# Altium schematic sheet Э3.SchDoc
size 594 x 420 mm; CheckedBy: Шилкин Д. А.; Author: Шестаков А. А.
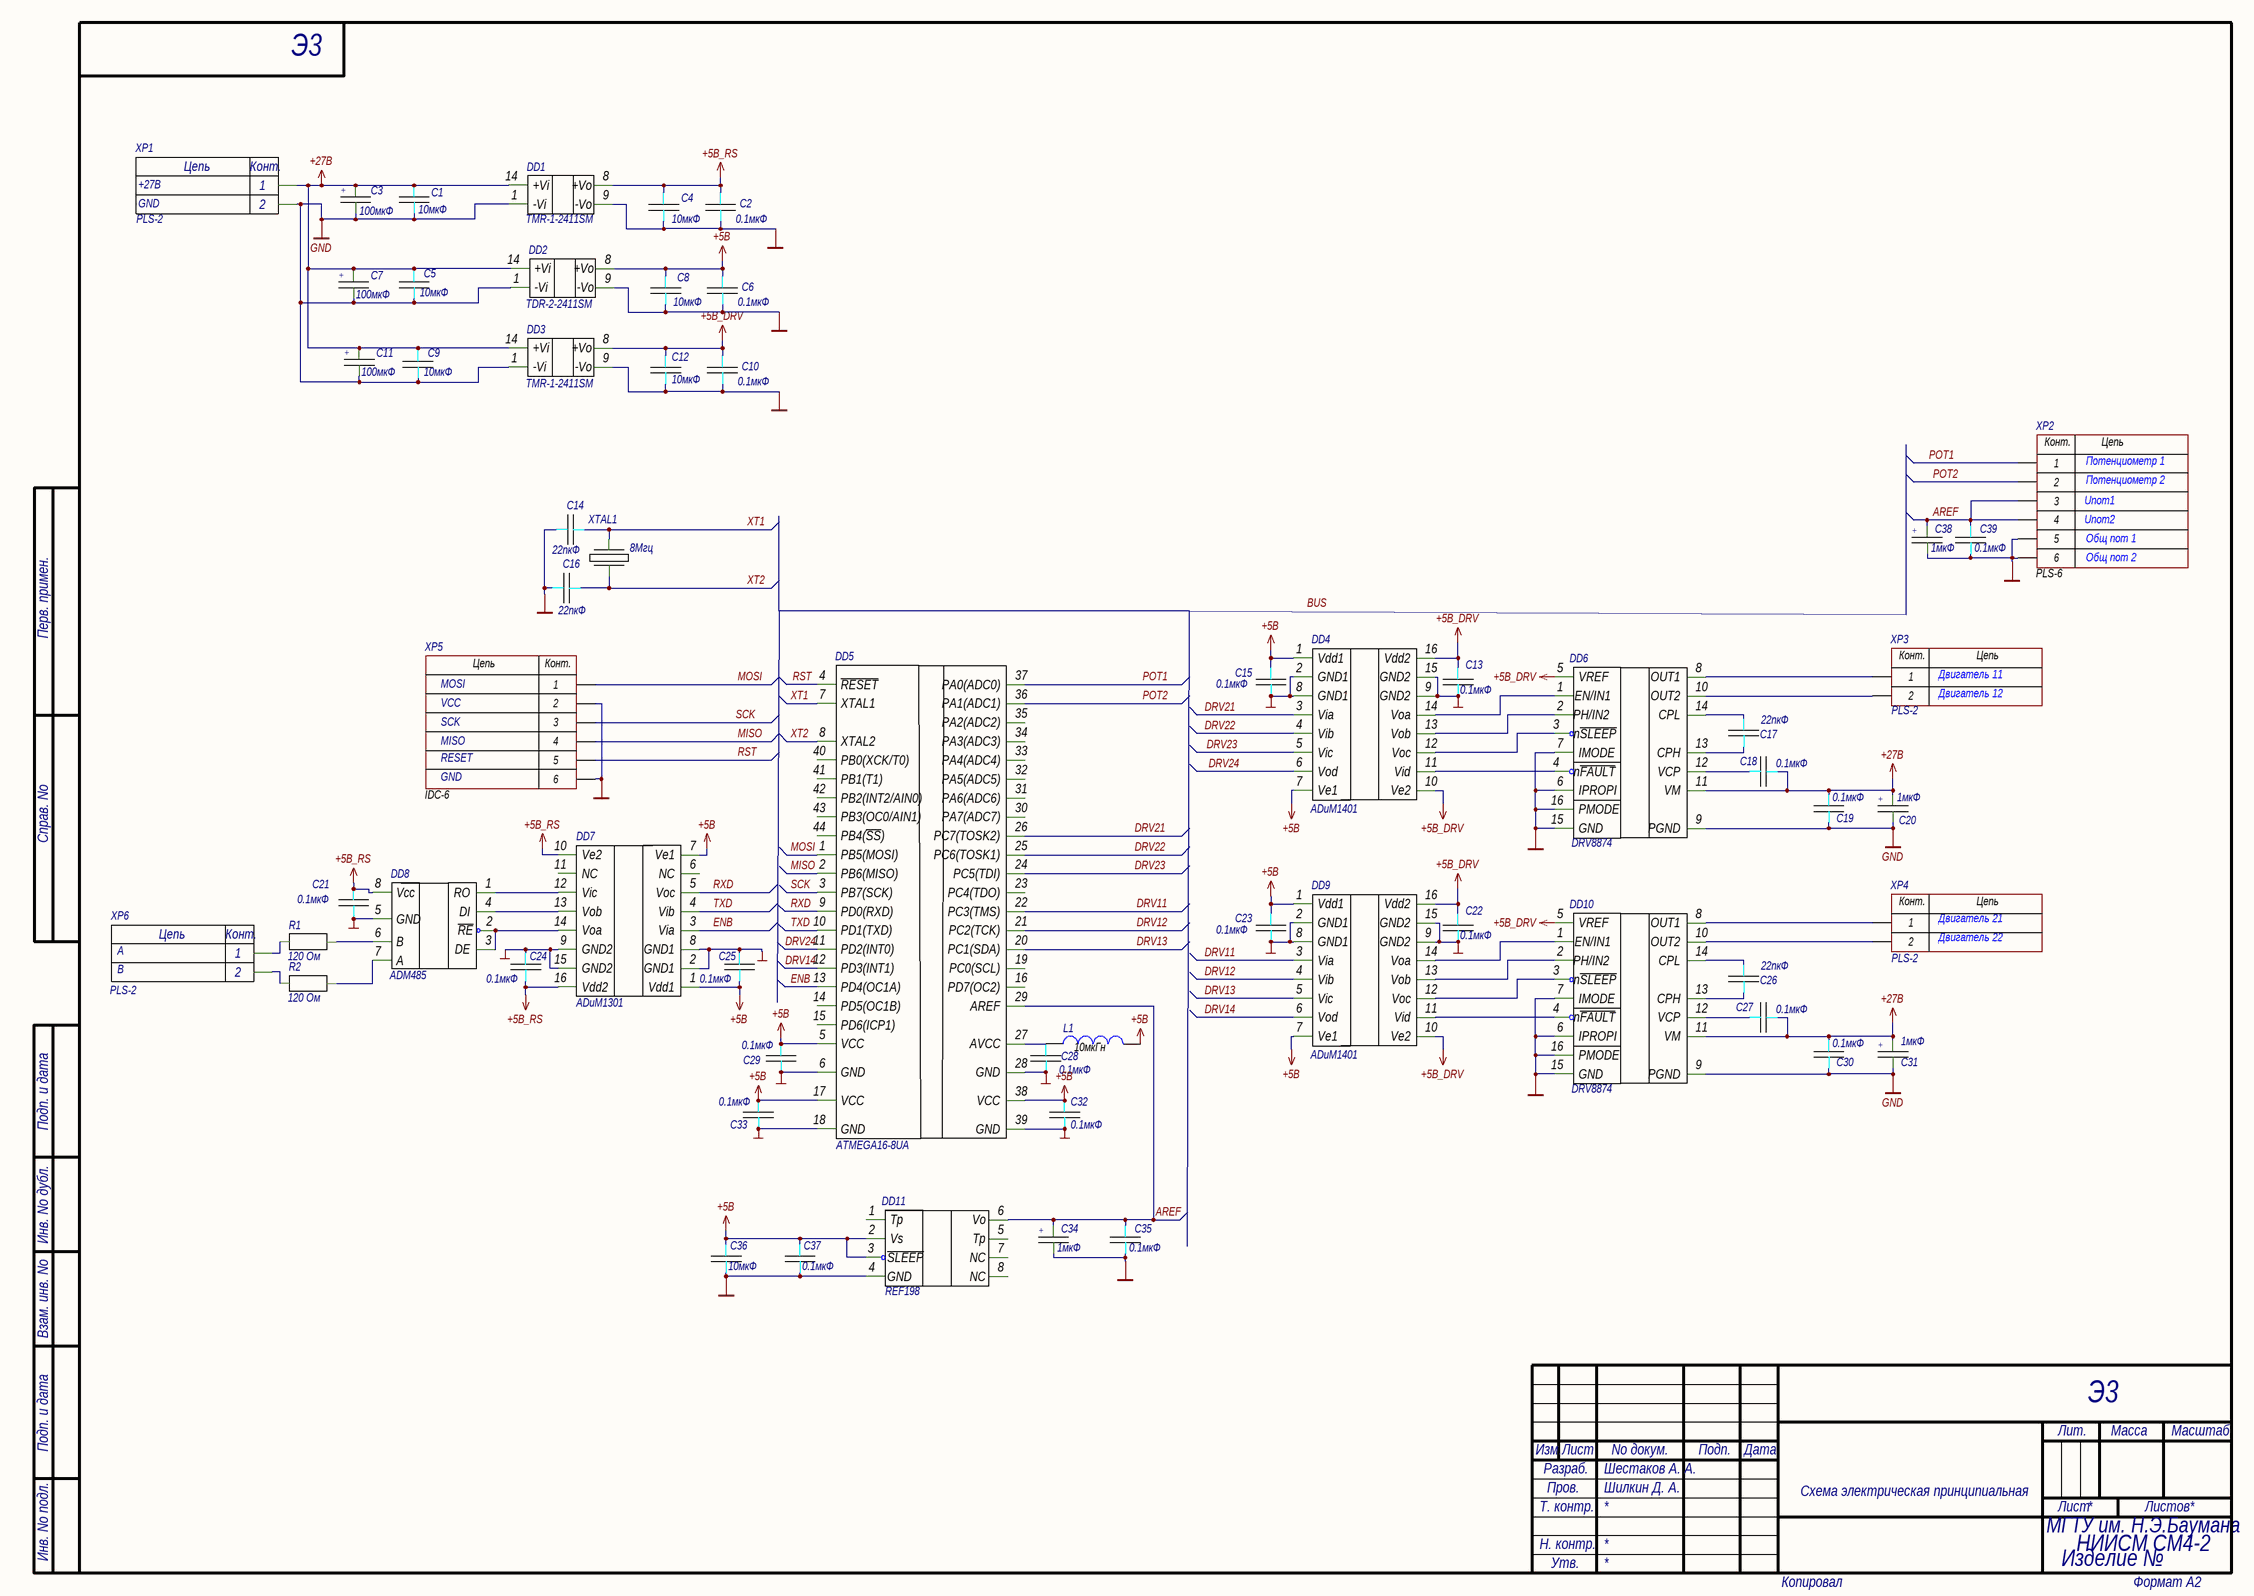
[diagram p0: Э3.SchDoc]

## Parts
C1  10мкФ  [Capacitor_0805]
C2  0.1мкФ  [Capacitor_0805]
C3  100мкФ  [CAPAE4643X46M]
C4  10мкФ  [Capacitor_0805]
C5  10мкФ  [Capacitor_0805]
C6  0.1мкФ  [Capacitor_0805]
C7  100мкФ  [CAPAE4643X46M]
C8  10мкФ  [Capacitor_0805]
C9  10мкФ  [Capacitor_0805]
C10  0.1мкФ  [Capacitor_0805]
C11  100мкФ  [CAPAE4643X46M]
C12  10мкФ  [Capacitor_0805]
C13  0.1мкФ  [Capacitor_0805]
C14  22пкФ  [Capacitor_0805]
C15  0.1мкФ  [Capacitor_0805]
C16  22пкФ  [Capacitor_0805]
C17  22пкФ  [Capacitor_0805]
C18  0.1мкФ  [Capacitor_0805]
C19  0.1мкФ  [Capacitor_0805]
C20  1мкФ  [Capacitor_tant_0805]
C21  0.1мкФ  [Capacitor_0805]
C22  0.1мкФ  [Capacitor_0805]
C23  0.1мкФ  [Capacitor_0805]
C24  0.1мкФ  [Capacitor_0805]
C25  0.1мкФ  [Capacitor_0805]
C26  22пкФ  [Capacitor_0805]
C27  0.1мкФ  [Capacitor_0805]
C28  0.1мкФ  [Capacitor_0805]
C29  0.1мкФ  [Capacitor_0805]
C30  0.1мкФ  [Capacitor_0805]
C31  1мкФ  [Capacitor_tant_0805]
C32  0.1мкФ  [Capacitor_0805]
C33  0.1мкФ  [Capacitor_0805]
C34  1мкФ  [Capacitor_tant_0805]
C35  0.1мкФ  [Capacitor_0805]
C36  10мкФ  [Capacitor_0805]
C37  0.1мкФ  [Capacitor_0805]
C38  1мкФ  [Capacitor_tant_0805]
C39  0.1мкФ  [Capacitor_0805]
DD1  TMR-1-2411SM  [TMR1SM_SMD]
DD2  TDR-2-2411SM  [TMR1SM_SMD]
DD3  TMR-1-2411SM  [TMR1SM_SMD]
DD4  ADuM1401  [ADUM_SOIC]
DD5  ATMEGA16-8UA  [ATMEGA16-44A]
DD6  DRV8874  [DRV8874_TSOP127P600-8N]
DD7  ADuM1301  [ADUM_SOIC]
DD8  ADM485  [SOIC_N8 (REF198, ADM485)]
DD9  ADuM1401  [ADUM_SOIC]
DD10  DRV8874  [DRV8874_TSOP127P600-8N]
DD11  REF198  [SOIC_N8 (REF198, ADM485)]
L1  value 10мкГн  [IND: 0805]
R1  120 Ом  [resistor_0805]
R2  120 Ом  [resistor_0805]
XP1  PLS-2  [CON: PLS-2]
XP2  (no value)  [CON: PLS-6]
XP3  PLS-2  [CON: PLS-2]
XP4  PLS-2  [CON: PLS-2]
XP5  (no value)  [CON: IDC-6MS]
XP6  PLS-2  [CON: PLS-2]
XTAL1  8Мгц  [Z_0503]

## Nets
+5B: C6.1 C8.1 C15.1 C23.1 C25.1 C29.1 C32.1 C33.1 C36.1 C37.1 DD2.8(+Vo) DD4.1(Vdd1) DD4.7(Ve1) DD5.5(VCC) DD5.17(VCC) DD5.38(VCC) DD7.1(Vdd1) DD7.7(Ve1) DD9.1(Vdd1) DD9.7(Ve1) DD11.2(Vs) DD11.3(~{SLEEP}) L1.1
+5B_DRV: C10.1 C12.1 C13.1 C22.1 DD3.8(+Vo) DD4.10(Ve2) DD4.16(Vdd2) DD6.5(VREF) DD9.10(Ve2) DD9.16(Vdd2) DD10.5(VREF)
+5B_RS: C2.1 C4.1 C21.2 C24.1 DD1.8(+Vo) DD7.10(Ve2) DD7.16(Vdd2) DD8.8(Vcc)
+27B: C1.1 C3.1 C5.1 C7.1 C9.1 C11.1 C18.2 C19.1 C20.1 C27.2 C30.1 C31.1 DD1.14(+Vi) DD2.14(+Vi) DD3.14(+Vi) DD6.11(VM) DD10.11(VM) XP1.1
GND: C1.2 C3.2 C5.2 C7.2 C9.2 C11.2 C19.2 C20.2 C30.2 C31.2 DD1.1(-Vi) DD2.1(-Vi) DD3.1(-Vi) DD6.9(PGND) DD10.9(PGND) XP1.2
Общ: C6.2 C8.2 C14.2 C15.2 C16.2 C23.2 C25.2 C28.2 C29.2 C32.2 C33.2 C34.2 C35.2 C36.2 C37.2 C38.2 C39.2 DD2.9(-Vo) DD4.2(GND1) DD4.8(GND1) DD5.6(GND) DD5.18(GND) DD5.28(GND) DD5.39(GND) DD7.2(GND1) DD7.8(GND1) DD9.2(GND1) DD9.8(GND1) DD11.4(GND) XP2.5 XP2.6 XP5.2 XP5.6
Общ_DRV: C10.2 C12.2 C13.2 C22.2 DD3.9(-Vo) DD4.9(GND2) DD4.15(GND2) DD6.6(IPROPI) DD6.7(IMODE) DD6.15(GND) DD6.16(PMODE) DD9.9(GND2) DD9.15(GND2) DD10.6(IPROPI) DD10.7(IMODE) DD10.15(GND) DD10.16(PMODE)
Общ_RS: C2.2 C4.2 C21.1 C24.2 DD1.9(-Vo) DD7.9(GND2) DD7.15(GND2) DD8.5(GND)
AREF: C34.1 C35.1 C38.1 C39.1 DD5.29(AREF) DD11.6(Vo) XP2.3 XP2.4
DRV11: DD5.22(PC3(TMS)) DD9.3(Via)
DRV12: DD5.21(PC2(TCK)) DD9.4(Vib)
DRV13: DD5.20(PC1(SDA)) DD9.5(Vic)
DRV14: DD5.12(PD3(INT1)) DD9.6(Vod)
DRV21: DD4.3(Via) DD5.26(PC7(TOSK2))
DRV22: DD4.4(Vib) DD5.25(PC6(TOSK1))
DRV23: DD4.5(Vic) DD5.24(PC5(TDI))
DRV24: DD4.6(Vod) DD5.11(PD2(INT0))
ENB: DD5.13(PD4(OC1A)) DD7.3(Via)
MISO: DD5.2(PB6(MISO)) XP5.4
MOSI: DD5.1(PB5(MOSI)) XP5.1
POT1: DD5.37(PA0(ADC0)) XP2.1
POT2: DD5.36(PA1(ADC1)) XP2.2
RST: DD5.4(~{RESET}) XP5.5
RXD: DD5.9(PD0(RXD)) DD7.5(Voc)
SCK: DD5.3(PB7(SCK)) XP5.3
TXD: DD5.10(PD1(TXD)) DD7.4(Vib)
XT1: C14.1 DD5.7(XTAL1) XTAL1.2
XT2: C16.1 DD5.8(XTAL2) XTAL1.1
NetC17_1: C17.1 DD6.14(CPL)
NetC17_2: C17.2 DD6.13(CPH)
NetC18_1: C18.1 DD6.12(VCP)
NetC26_1: C26.1 DD10.14(CPL)
NetC26_2: C26.2 DD10.13(CPH)
NetC27_1: C27.1 DD10.12(VCP)
NetC28_1: C28.1 DD5.27(AVCC) L1.2
NetDD4_11: DD4.11(Vid) DD6.4(n~{FAULT})
NetDD4_12: DD4.12(Voc) DD6.3(n~{SLEEP})
NetDD4_13: DD4.13(Vob) DD6.2(PH/IN2)
NetDD4_14: DD4.14(Voa) DD6.1(EN/IN1)
NetDD6_8: DD6.8(OUT1) XP3.1
NetDD6_10: DD6.10(OUT2) XP3.2
NetDD7_12: DD7.12(Vic) DD8.1(RO)
NetDD7_13: DD7.13(Vob) DD8.4(DI)
NetDD7_14: DD7.14(Voa) DD8.2(~{RE}) DD8.3(DE)
NetDD8_6: DD8.6(B) R1.1
NetDD8_7: DD8.7(A) R2.1
NetDD9_11: DD9.11(Vid) DD10.4(n~{FAULT})
NetDD9_12: DD9.12(Voc) DD10.3(n~{SLEEP})
NetDD9_13: DD9.13(Vob) DD10.2(PH/IN2)
NetDD9_14: DD9.14(Voa) DD10.1(EN/IN1)
NetDD10_8: DD10.8(OUT1) XP4.1
NetDD10_10: DD10.10(OUT2) XP4.2
NetR1_0: R1.0 XP6.1
NetR2_0: R2.0 XP6.2

Not connected (* = marked no-connect by the designer): DD5 14(PD5(OC1B)) 15(PD6(ICP1)) 16(PD7(OC2)) 19(PC0(SCL)) 23(PC4(TDO)) 30(PA7(ADC7)) 31(PA6(ADC6)) 32(PA5(ADC5)) 33(PA4(ADC4)) 34(PA3(ADC3)) 35(PA2(ADC2)) 40(PB0(XCK/T0)) 41(PB1(T1)) 42(PB2(INT2/AIN0)) 43(PB3(OC0/AIN1)) 44(PB4(~{SS})); DD7 6(NC) 11(NC); DD11 1(Tp) 5(Tp) 7(NC) 8(NC)

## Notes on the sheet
- +27В
- GND
- Uпот1
- Потенциометр 1
- Потенциометр 2
- Uпот2
- Общ пот 1
- Общ пот 2
- MOSI
- Двигатель 11
- Двигатель 12
- MISO
- VCC
- SCK
- RESET
- Двигатель 21
- A
- B
- Двигатель 22
- Labels drawn without touching a wire or pin: BUS

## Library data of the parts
C1 C2 C4-C6 C8-C10 C12-C19 C21-C30 C32 C33 C35-C37 C39 = Capacity_0805
C3 C7 C11 = Capacity_electrolity_polar_0805: electrolity capacitor
C20 C31 C34 C38 = Capacity_tantal_0805: tanral capacitor
DD5 = ATMEGA16-44A
L1 = Inductor_0805: Manufacturer: Murata Electronics; PartNumber: LQM21FN100M70L; ValueManufacturerPartNumber: Fixed inductor, 10мкГн, ±20%, 0805, 100mA, -55...+125°C; TypeInductor: Fixed inductor; MaxCurrent: 100mA; Tolerance: ±20%
R1 R2 = Resistor_0805
XP1 XP6 = PLS-2: https://www.chipdip.ru/product/wf-2r
XP2 = PLS-6: Manufacturer: Connfly; ValueManufacturerPartNumber: Connector, 6pin, 2.54mm, 500VAC, 3A; TypeConnector: Connector; VoltageMax: 500VAC; Pitch: 2.54mm; CurrentMax: 3A; Multichannel: 6pin
XP3 XP4 = PLS-2-1
XP5 = IDC-6: Manufacturer: Connfly; ValueManufacturerPartNumber: Connector, 6pin, 2.54mm, 500VAC, 3A; PartNumber: PLS-6; TypeConnector: Connector; VoltageMax: 500VAC; Pitch: 2.54mm; CurrentMax: 3A; Multichannel: 6pin
XTAL1 = resonstor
